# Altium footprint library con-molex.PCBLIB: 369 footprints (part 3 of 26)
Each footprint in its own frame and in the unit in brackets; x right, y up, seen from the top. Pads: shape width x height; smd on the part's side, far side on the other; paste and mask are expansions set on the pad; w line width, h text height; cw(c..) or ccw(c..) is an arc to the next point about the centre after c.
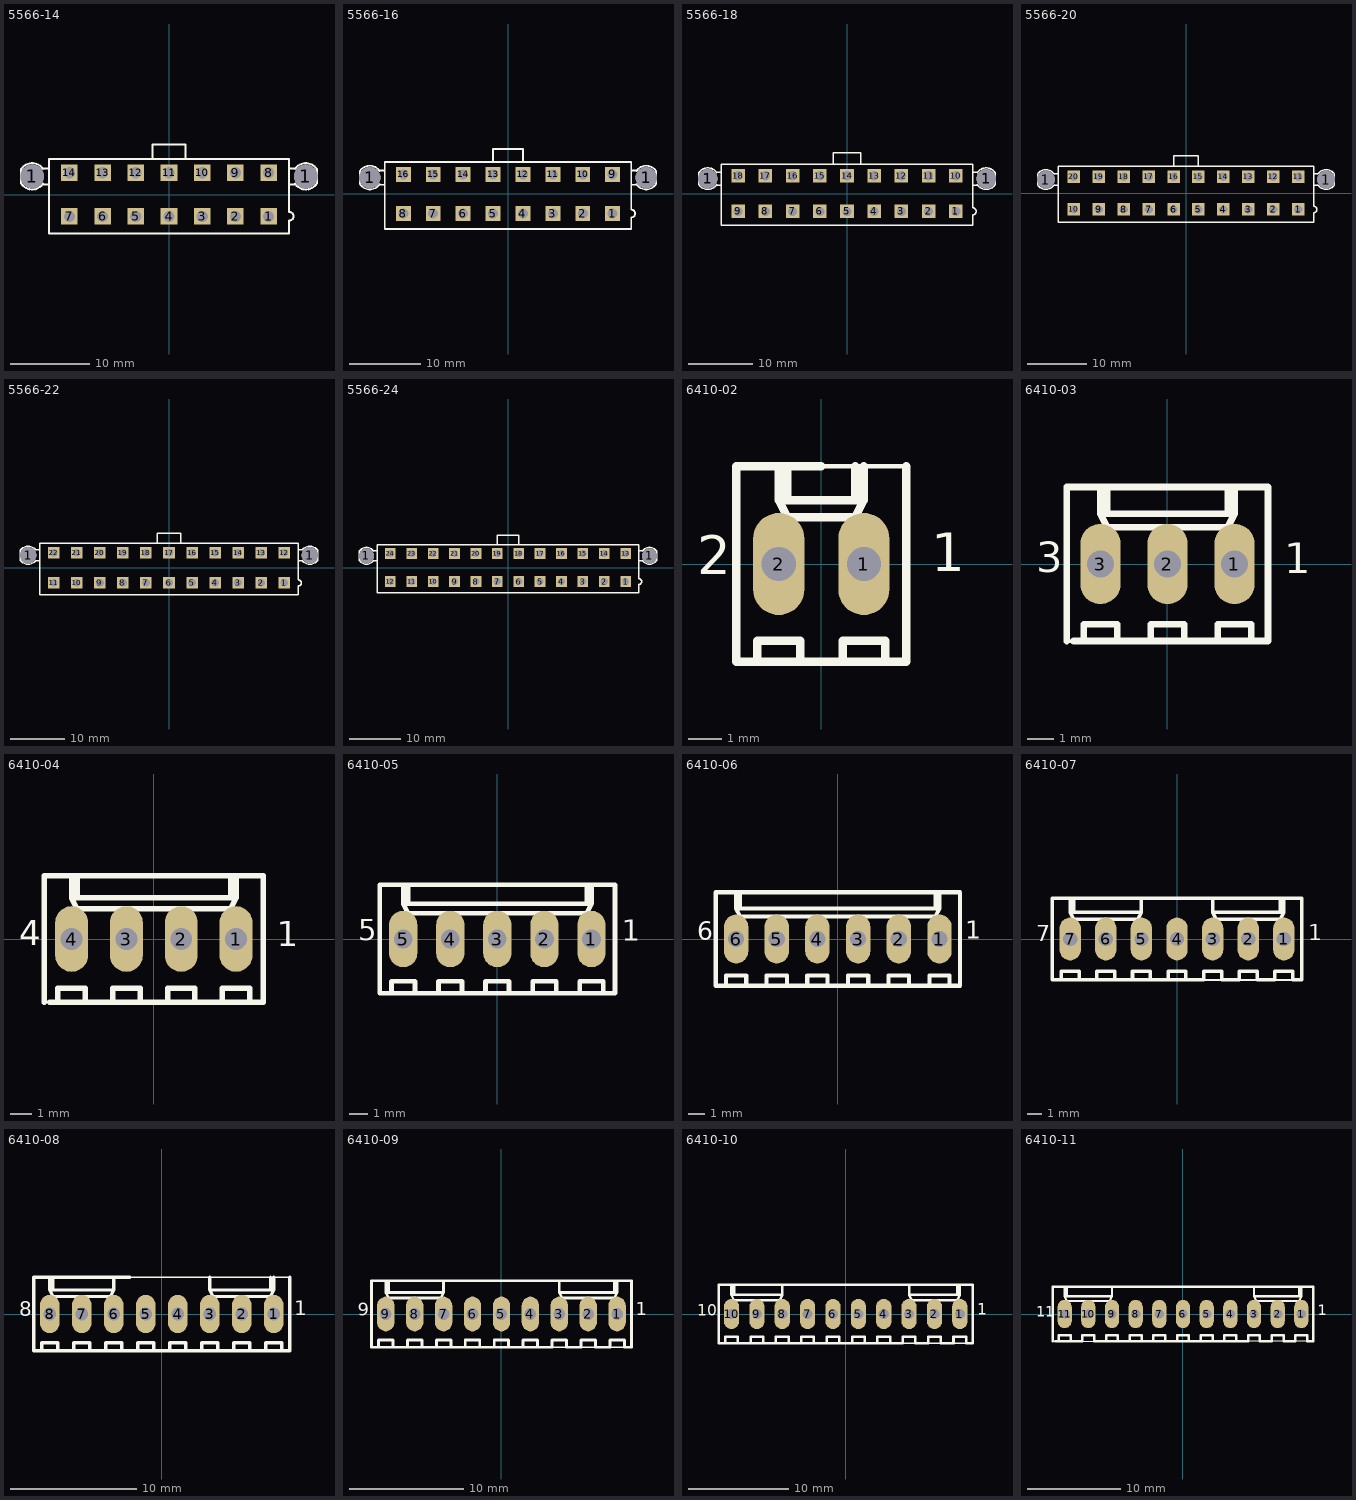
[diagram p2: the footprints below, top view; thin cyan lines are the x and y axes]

## 5566-14 [mm]
pads (16):
  round 3 hole 3: 1(-17.3,2.29) 1(17.3,2.29)
  rect 2.1x2.1 hole 1.4: 1(12.6,-2.75) 2(8.4,-2.75) 3(4.2,-2.75) 4(0,-2.75) 5(-4.2,-2.75) 6(-8.4,-2.75) 7(-12.6,-2.75) 8(12.6,2.75) 9(8.4,2.75) 10(4.2,2.75) 11(0,2.75) 12(-4.2,2.75) 13(-8.4,2.75) 14(-12.6,2.75)
Top Overlay:
  lines w0.254: -16,1.3 -15.3,1.3 ; -16,3.3 -15.3,3.3 ; -15.9,1.4 cw(c-17.3,2.3) -18.7,1.4 -18.7,3.2 cw(c-17.3,2.3) -15.9,3.2 ; -2.1,4.6 -2.1,6.3 2.1,6.3 2.1,4.6 ; 15.3,1.3 16,1.3 ; 15.3,3.3 16,3.3 ; 15.9,1.4 ccw(c17.3,2.3) 18.7,1.4 18.7,3.2 ccw(c17.3,2.3) 15.9,3.2 ; -15.2,-4.9 15.2,-4.9 15.2,-3.3 ccw(c15.2,-2.75) 15.2,-2.2 15.2,4.5 -15.2,4.5 -15.2,-4.9

## 5566-16 [mm]
pads (18):
  round 3 hole 3: 1(-19.4,2.29) 1(19.4,2.29)
  rect 2.1x2.1 hole 1.4: 1(14.7,-2.75) 2(10.5,-2.75) 3(6.3,-2.75) 4(2.1,-2.75) 5(-2.1,-2.75) 6(-6.3,-2.75) 7(-10.5,-2.75) 8(-14.7,-2.75) 9(14.7,2.75) 10(10.5,2.75) 11(6.3,2.75) 12(2.1,2.75) 13(-2.1,2.75) 14(-6.3,2.75) 15(-10.5,2.75) 16(-14.7,2.75)
Top Overlay:
  lines w0.254: -18.1,1.3 -17.4,1.3 ; -18.1,3.3 -17.4,3.3 ; -18,1.4 cw(c-19.4,2.3) -20.8,1.4 -20.8,3.2 cw(c-19.4,2.3) -18,3.2 ; -2.1,4.6 -2.1,6.3 2.1,6.3 2.1,4.6 ; 17.4,1.3 18.1,1.3 ; 17.4,3.3 18.1,3.3 ; 18,1.4 ccw(c19.4,2.3) 20.8,1.4 20.8,3.2 ccw(c19.4,2.3) 18,3.2 ; -17.3,-4.9 17.3,-4.9 17.3,-3.3 ccw(c17.3,-2.75) 17.3,-2.2 17.3,4.5 -17.3,4.5 -17.3,-4.9

## 5566-18 [mm]
pads (20):
  round 3 hole 3: 1(-21.5,2.29) 1(21.5,2.29)
  rect 2.1x2.1 hole 1.4: 1(16.8,-2.75) 2(12.6,-2.75) 3(8.4,-2.75) 4(4.2,-2.75) 5(0,-2.75) 6(-4.2,-2.75) 7(-8.4,-2.75) 8(-12.6,-2.75) 9(-16.8,-2.75) 10(16.8,2.75) 11(12.6,2.75) 12(8.4,2.75) 13(4.2,2.75) 14(0,2.75) 15(-4.2,2.75) 16(-8.4,2.75) 17(-12.6,2.75) 18(-16.8,2.75)
Top Overlay:
  lines w0.254: -20.2,1.3 -19.5,1.3 ; -20.2,3.3 -19.5,3.3 ; -20.1,1.4 cw(c-21.5,2.3) -22.9,1.4 -22.9,3.2 cw(c-21.5,2.3) -20.1,3.2 ; -2.1,4.6 -2.1,6.3 2.1,6.3 2.1,4.6 ; 19.5,1.3 20.2,1.3 ; 19.5,3.3 20.2,3.3 ; 20.1,1.4 ccw(c21.5,2.3) 22.9,1.4 22.9,3.2 ccw(c21.5,2.3) 20.1,3.2 ; -19.4,-4.9 19.4,-4.9 19.4,-3.3 ccw(c19.4,-2.75) 19.4,-2.2 19.4,4.5 -19.4,4.5 -19.4,-4.9

## 5566-20 [mm]
pads (22):
  round 3 hole 3: 1(-23.6,2.29) 1(23.6,2.29)
  rect 2.1x2.1 hole 1.4: 1(18.9,-2.75) 2(14.7,-2.75) 3(10.5,-2.75) 4(6.3,-2.75) 5(2.1,-2.75) 6(-2.1,-2.75) 7(-6.3,-2.75) 8(-10.5,-2.75) 9(-14.7,-2.75) 10(-18.9,-2.75) 11(18.9,2.75) 12(14.7,2.75) 13(10.5,2.75) 14(6.3,2.75) 15(2.1,2.75) 16(-2.1,2.75) 17(-6.3,2.75) 18(-10.5,2.75) 19(-14.7,2.75) 20(-18.9,2.75)
Top Overlay:
  lines w0.254: -22.3,1.3 -21.6,1.3 ; -22.3,3.3 -21.6,3.3 ; -22.2,1.4 cw(c-23.6,2.3) -25,1.4 -25,3.2 cw(c-23.6,2.3) -22.2,3.2 ; -2.1,4.6 -2.1,6.3 2.1,6.3 2.1,4.6 ; 21.6,1.3 22.3,1.3 ; 21.6,3.3 22.3,3.3 ; 22.2,1.4 ccw(c23.6,2.3) 25,1.4 25,3.2 ccw(c23.6,2.3) 22.2,3.2 ; -21.5,-4.9 21.5,-4.9 21.5,-3.3 ccw(c21.5,-2.75) 21.5,-2.2 21.5,4.5 -21.5,4.5 -21.5,-4.9

## 5566-22 [mm]
pads (24):
  round 3 hole 3: 1(-25.7,2.29) 1(25.7,2.29)
  rect 2.1x2.1 hole 1.4: 1(21,-2.75) 2(16.8,-2.75) 3(12.6,-2.75) 4(8.4,-2.75) 5(4.2,-2.75) 6(0,-2.75) 7(-4.2,-2.75) 8(-8.4,-2.75) 9(-12.6,-2.75) 10(-16.8,-2.75) 11(-21,-2.75) 12(21,2.75) 13(16.8,2.75) 14(12.6,2.75) 15(8.4,2.75) 16(4.2,2.75) 17(0,2.75) 18(-4.2,2.75) 19(-8.4,2.75) 20(-12.6,2.75) 21(-16.8,2.75) 22(-21,2.75)
Top Overlay:
  lines w0.254: -24.4,1.3 -23.7,1.3 ; -24.4,3.3 -23.7,3.3 ; -24.3,1.4 cw(c-25.7,2.3) -27.1,1.4 -27.1,3.2 cw(c-25.7,2.3) -24.3,3.2 ; -2.1,4.6 -2.1,6.3 2.1,6.3 2.1,4.6 ; 23.7,1.3 24.4,1.3 ; 23.7,3.3 24.4,3.3 ; 24.3,1.4 ccw(c25.7,2.3) 27.1,1.4 27.1,3.2 ccw(c25.7,2.3) 24.3,3.2 ; -23.6,-4.9 23.6,-4.9 23.6,-3.3 ccw(c23.6,-2.75) 23.6,-2.2 23.6,4.5 -23.6,4.5 -23.6,-4.9

## 5566-24 [mm]
pads (26):
  round 3 hole 3: 1(-27.8,2.29) 1(27.8,2.29)
  rect 2.1x2.1 hole 1.4: 1(23.1,-2.75) 2(18.9,-2.75) 3(14.7,-2.75) 4(10.5,-2.75) 5(6.3,-2.75) 6(2.1,-2.75) 7(-2.1,-2.75) 8(-6.3,-2.75) 9(-10.5,-2.75) 10(-14.7,-2.75) 11(-18.9,-2.75) 12(-23.1,-2.75) 13(23.1,2.75) 14(18.9,2.75) 15(14.7,2.75) 16(10.5,2.75) 17(6.3,2.75) 18(2.1,2.75) 19(-2.1,2.75) 20(-6.3,2.75) 21(-10.5,2.75) 22(-14.7,2.75) 23(-18.9,2.75) 24(-23.1,2.75)
Top Overlay:
  lines w0.254: -26.5,1.3 -25.8,1.3 ; -26.5,3.3 -25.8,3.3 ; -26.4,1.4 cw(c-27.8,2.3) -29.2,1.4 -29.2,3.2 cw(c-27.8,2.3) -26.4,3.2 ; -2.1,4.6 -2.1,6.3 2.1,6.3 2.1,4.6 ; 25.8,1.3 26.5,1.3 ; 25.8,3.3 26.5,3.3 ; 26.4,1.4 ccw(c27.8,2.3) 29.2,1.4 29.2,3.2 ccw(c27.8,2.3) 26.4,3.2 ; -25.7,-4.9 25.7,-4.9 25.7,-3.3 ccw(c25.7,-2.75) 25.7,-2.2 25.7,4.5 -25.7,4.5 -25.7,-4.9

## 6410-02 [mil]
pads (2):
  oval 60x120 hole 40: 1(50,0) 2(-50,0)
Top Overlay:
  lines w5: -90,-115 -75,-115 ; -50,100 -50,115 -40,115 ; 0,-115 25,-115 ; 0,115 100,115 ; 75,-115 100,-115
  lines w10: -40,115 -40,75 ; 0,-115 -100,-115 ; 0,115 -50,115 ; 40,115 40,75 ; 50,115 50,75 ; 100,115 100,0 100,-115 75,-115 ; -100,-115 -100,0 -100,115 -50,115 ; -100,-115 -75,-115 -75,-90 -25,-90 -25,-115 25,-115 ; -50,75 -50,115 ; -50,75 -40,75 ; -50,75 -40,55 40,55 50,75 ; -40,75 40,75 ; 25,-115 75,-115 ; 25,-115 25,-90 75,-90 75,-115 ; 40,75 50,75
  text "1" at 128.94,-24.06 h77.5
  text "2" at -146.06,-27.06 h77.5
Mechanical 16:
  rectangle: -60,-10 -40,10
  rectangle: 40,-10 60,10

## 6410-03 [mil]
pads (3):
  oval 60x120 hole 40: 1(100,0) 2(0,0) 3(-100,0)
Top Overlay:
  lines w5: -150,-115 -50,-115 -25,-115 ; -100,100 -100,115 -90,115
  lines w10: -150,-115 -150,0 -150,115 -100,115 ; -140,-115 -125,-115 ; -90,115 -90,75 ; 90,115 90,75 ; 100,115 100,75 ; -125,-115 -125,-90 -75,-90 -75,-115 ; -125,-115 -75,-115 ; -100,75 -100,115 ; -100,75 -90,75 ; -100,75 -90,55 90,55 100,75 ; -100,115 -50,115 150,115 150,0 150,-115 125,-115 ; -90,75 90,75 ; -75,-115 -25,-115 ; -25,-115 25,-115 ; -25,-115 -25,-90 25,-90 25,-115 ; 25,-115 75,-115 ; 75,-115 125,-115 ; 75,-115 75,-90 125,-90 125,-115 ; 90,75 100,75
  text "1" at 173.94,-29.06 h77.5
  text "3" at -196.06,-27.06 h77.5
Mechanical 16:
  rectangle: -110,-10 -90,10
  rectangle: -10,-10 10,10
  rectangle: 90,-10 110,10

## 6410-04 [mil]
pads (4):
  oval 60x120 hole 40: 1(150,0) 2(50,0) 3(-50,0) 4(-150,0)
Top Overlay:
  lines w5: -200,-115 -105,-115 ; -150,100 -150,115 -140,115
  lines w10: -200,-115 -200,0 -200,115 -150,115 ; -190,-115 -175,-115 ; -140,115 -140,75 ; -105,-115 200,-115 ; 140,115 140,75 ; 150,115 150,75 ; -175,-115 -175,-90 -125,-90 -125,-115 -75,-115 -75,-90 -25,-90 -25,-115 ; -175,-115 -25,-115 ; -150,75 -150,115 ; -150,75 -140,75 ; -150,75 -140,55 140,55 150,75 ; -150,115 -100,115 200,115 200,0 200,-115 ; -140,75 140,75 ; -25,-115 25,-115 25,-90 75,-90 75,-115 125,-115 125,-90 175,-90 175,-115 200,-115 ; 140,75 150,75
  text "1" at 223.94,-29.06 h77.5
  text "4" at -246.06,-27.06 h77.5
Mechanical 16:
  rectangle: -160,-10 -140,10
  rectangle: -60,-10 -40,10
  rectangle: 40,-10 60,10
  rectangle: 140,-10 160,10

## 6410-05 [mil]
pads (5):
  oval 60x120 hole 40: 1(200,0) 2(100,0) 3(0,0) 4(-100,0) 5(-200,0)
Top Overlay:
  lines w5: -200,100 -200,115
  lines w10: -240,-115 -225,-115 -225,-90 -175,-90 -175,-115 -125,-115 -125,-90 -75,-90 -75,-115 -25,-115 ; 50,-115 -250,-115 -250,0 -250,115 -200,115 ; 190,115 190,75 ; 200,115 200,75 ; -200,75 -200,115 ; -200,75 -190,75 ; -200,75 -190,55 190,55 200,75 ; -200,115 -190,115 ; -190,75 190,75 ; -190,75 -190,115 ; -190,115 50,115 250,115 250,0 250,-115 225,-115 ; -25,-115 -25,-90 25,-90 25,-115 ; -25,-115 25,-115 ; 25,-115 75,-115 ; 75,-115 125,-115 ; 75,-115 75,-90 125,-90 125,-115 ; 125,-115 175,-115 ; 175,-115 225,-115 ; 175,-115 175,-90 225,-90 225,-115 ; 190,75 200,75
  text "1" at 263.94,-19.06 h77.5
  text "5" at -296.06,-17.06 h77.5
Mechanical 16:
  rectangle: -10,-10 10,10
  rectangle: 90,-10 110,10
  rectangle: 190,-10 210,10
  rectangle: -110,-10 -90,10
  rectangle: -210,-10 -190,10

## 6410-06 [mil]
pads (6):
  oval 60x120 hole 40: 1(250,0) 2(150,0) 3(50,0) 4(-50,0) 5(-150,0) 6(-250,0)
Top Overlay:
  lines w5: -250,100 -250,115
  lines w10: -290,-115 -275,-115 -275,-90 -225,-90 -225,-115 -175,-115 -175,-90 -125,-90 -125,-115 -75,-115 -75,-90 -25,-90 -25,-115 25,-115 25,-90 75,-90 75,-115 125,-115 125,-90 175,-90 175,-115 225,-115 225,-90 275,-90 275,-115 300,-115 ; 240,115 240,75 ; 250,115 250,75 ; -250,75 -250,115 ; -250,75 -240,75 ; -250,75 -240,55 240,55 250,75 ; -250,115 -300,115 -300,0 -300,-115 -5,-115 300,-115 ; -250,115 -240,115 ; -240,75 240,75 ; -240,75 -240,115 ; -240,115 0,115 300,115 300,0 300,-115 ; 240,75 250,75
  text "1" at 313.94,-14.06 h77.5
  text "6" at -346.06,-17.06 h77.5
Mechanical 16:
  rectangle: -260,-10 -240,10
  rectangle: -160,-10 -140,10
  rectangle: -60,-10 -40,10
  rectangle: 40,-10 60,10
  rectangle: 140,-10 160,10
  rectangle: 240,-10 260,10

## 6410-07 [mil]
pads (7):
  oval 60x120 hole 40: 1(300,0) 2(200,0) 3(100,0) 4(0,0) 5(-100,0) 6(-200,0) 7(-300,0)
Top Overlay:
  lines w5: -300,100 -300,115 ; -55,-115 350,-115
  lines w10: -340,-115 -325,-115 -325,-90 -275,-90 -275,-115 -225,-115 -225,-90 -175,-90 -175,-115 -125,-115 -125,-90 -75,-90 -75,-115 75,-115 75,-90 125,-90 125,-115 175,-115 175,-90 225,-90 225,-115 275,-115 275,-90 325,-90 325,-115 350,-115 350,0 350,115 -50,115 -100,115 ; -55,-115 -350,-115 -350,0 -350,115 -300,115 ; -25,-115 -25,-90 25,-90 25,-115 ; 100,115 100,75 ; 290,115 290,75 ; 300,115 300,75 ; -300,75 -300,115 ; -300,75 -290,75 ; -300,75 -290,55 -110,55 -100,75 ; -300,115 -290,115 ; -290,75 -100,75 ; -290,75 -290,115 ; -290,115 -100,115 ; -100,75 -100,115 ; 100,75 290,75 ; 100,75 110,55 290,55 300,75 ; 290,75 300,75
  text "1" at 368.94,-19.06 h77.5
  text "7" at -396.06,-22.06 h77.5
Mechanical 16:
  rectangle: 90,-10 110,10
  rectangle: 190,-10 210,10
  rectangle: 290,-10 310,10
  rectangle: -10,-10 10,10
  rectangle: -110,-10 -90,10
  rectangle: -310,-10 -290,10
  rectangle: -210,-10 -190,10

## 6410-08 [mil]
pads (8):
  oval 60x120 hole 40: 1(350,0) 2(250,0) 3(150,0) 4(50,0) 5(-50,0) 6(-150,0) 7(-250,0) 8(-350,0)
Top Overlay:
  lines w5: -350,100 -350,115 ; -100,115 400,115
  lines w10: -390,-115 -375,-115 -375,-90 -325,-90 -325,-115 -275,-115 -275,-90 -225,-90 -225,-115 -175,-115 -175,-90 -125,-90 -125,-115 125,-115 125,-90 175,-90 175,-115 225,-115 225,-90 275,-90 275,-115 325,-115 325,-90 375,-90 375,-115 400,-115 ; -100,115 -150,115 ; -75,-115 -75,-90 -25,-90 -25,-115 ; 25,-115 25,-90 75,-90 75,-115 ; 150,115 150,75 ; 340,115 340,75 ; 350,115 350,75 ; 400,115 400,0 400,-115 ; -350,75 -350,115 ; -350,75 -340,75 ; -350,75 -340,55 -160,55 -150,75 ; -350,115 -400,115 -400,0 -400,-115 -105,-115 400,-115 ; -350,115 -340,115 ; -340,75 -150,75 ; -340,75 -340,115 ; -340,115 -150,115 ; -150,75 -150,115 ; 150,75 340,75 ; 150,75 160,55 340,55 350,75 ; 340,75 350,75
  text "1" at 413.94,-19.06 h77.5
  text "8" at -446.06,-22.06 h77.5
Mechanical 16:
  rectangle: -360,-10 -340,10
  rectangle: -260,-10 -240,10
  rectangle: -160,-10 -140,10
  rectangle: 140,-10 160,10
  rectangle: 240,-10 260,10
  rectangle: 340,-10 360,10
  rectangle: -60,-10 -40,10
  rectangle: 40,-10 60,10

## 6410-09 [mil]
pads (9):
  oval 60x120 hole 40: 1(400,0) 2(300,0) 3(200,0) 4(100,0) 5(0,0) 6(-100,0) 7(-200,0) 8(-300,0) 9(-400,0)
Top Overlay:
  lines w5: -400,100 -400,115 ; -155,-115 450,-115
  lines w10: -440,-115 -425,-115 -425,-90 -375,-90 -375,-115 -325,-115 -325,-90 -275,-90 -275,-115 -225,-115 -225,-90 -175,-90 -175,-115 175,-115 175,-90 225,-90 225,-115 275,-115 275,-90 325,-90 325,-115 375,-115 375,-90 425,-90 425,-115 450,-115 450,0 450,115 -150,115 -200,115 ; -155,-115 -450,-115 -450,0 -450,115 -400,115 ; -125,-115 -125,-90 -75,-90 -75,-115 ; -25,-115 -25,-90 25,-90 25,-115 ; 75,-115 75,-90 125,-90 125,-115 ; 200,115 200,75 ; 390,115 390,75 ; 400,115 400,75 ; -400,75 -400,115 ; -400,75 -390,75 ; -400,75 -390,55 -210,55 -200,75 ; -400,115 -390,115 ; -390,75 -200,75 ; -390,75 -390,115 ; -390,115 -200,115 ; -200,75 -200,115 ; 200,75 390,75 ; 200,75 210,55 390,55 400,75 ; 390,75 400,75
  text "1" at 463.94,-19.06 h77.5
  text "9" at -496.06,-22.06 h77.5
Mechanical 16:
  rectangle: 190,-10 210,10
  rectangle: 290,-10 310,10
  rectangle: 390,-10 410,10
  rectangle: -410,-10 -390,10
  rectangle: 90,-10 110,10
  rectangle: -10,-10 10,10
  rectangle: -310,-10 -290,10
  rectangle: -210,-10 -190,10
  rectangle: -110,-10 -90,10

## 6410-10 [mil]
pads (10):
  oval 60x120 hole 40: 1(450,0) 2(350,0) 3(250,0) 4(150,0) 5(50,0) 6(-50,0) 7(-150,0) 8(-250,0) 9(-350,0) 10(-450,0)
Top Overlay:
  lines w5: -450,100 -450,115 ; -205,-115 500,-115
  lines w10: -490,-115 -475,-115 -475,-90 -425,-90 -425,-115 -375,-115 -375,-90 -325,-90 -325,-115 -275,-115 -275,-90 -225,-90 -225,-115 225,-115 225,-90 275,-90 275,-115 325,-115 325,-90 375,-90 375,-115 425,-115 425,-90 475,-90 475,-115 500,-115 500,0 500,115 -200,115 -250,115 ; -205,-115 -500,-115 -500,0 -500,115 -450,115 ; -175,-115 -175,-90 -125,-90 -125,-115 ; -75,-115 -75,-90 -25,-90 -25,-115 ; 25,-115 25,-90 75,-90 75,-115 ; 125,-115 125,-90 175,-90 175,-115 ; 250,115 250,75 ; 440,115 440,75 ; 450,115 450,75 ; -450,75 -450,115 ; -450,75 -440,75 ; -450,75 -440,55 -260,55 -250,75 ; -450,115 -440,115 ; -440,75 -250,75 ; -440,75 -440,115 ; -440,115 -250,115 ; -250,75 -250,115 ; 250,75 440,75 ; 250,75 260,55 440,55 450,75 ; 440,75 450,75
  text "1" at 518.94,-19.06 h77.5
  text "10" at -586.06,-22.06 h77.5
Mechanical 16:
  rectangle: -460,-10 -440,10
  rectangle: -360,-10 -340,10
  rectangle: -260,-10 -240,10
  rectangle: 240,-10 260,10
  rectangle: 340,-10 360,10
  rectangle: 440,-10 460,10
  rectangle: -160,-10 -140,10
  rectangle: 140,-10 160,10
  rectangle: 40,-10 60,10
  rectangle: -60,-10 -40,10

## 6410-11 [mil]
pads (11):
  oval 60x120 hole 40: 1(500,0) 2(400,0) 3(300,0) 4(200,0) 5(100,0) 6(0,0) 7(-100,0) 8(-200,0) 9(-300,0) 10(-400,0) 11(-500,0)
Top Overlay:
  lines w5: -550,-115 -355,-115 550,-115 ; -500,100 -500,115
  lines w10: -550,-115 -550,0 -550,115 -500,115 ; -540,-115 -525,-115 ; -325,-115 -325,-90 -275,-90 -275,-115 ; -225,-115 -225,-90 -175,-90 -175,-115 ; -125,-115 -125,-90 -75,-90 -75,-115 ; -25,-115 -25,-90 25,-90 25,-115 ; 75,-115 75,-90 125,-90 125,-115 ; 175,-115 175,-90 225,-90 225,-115 ; 300,115 300,75 ; 490,115 490,75 ; 500,115 500,75 ; -525,-115 -475,-115 ; -525,-115 -525,-90 -475,-90 -475,-115 ; -500,75 -500,115 ; -500,75 -490,75 ; -500,75 -490,55 -310,55 -300,75 ; -500,115 -490,115 ; -490,75 -300,75 ; -490,75 -490,115 ; -490,115 -300,115 ; -475,-115 -425,-115 -425,-90 -375,-90 -375,-115 275,-115 275,-90 325,-90 325,-115 375,-115 375,-90 425,-90 425,-115 475,-115 475,-90 525,-90 525,-115 550,-115 550,0 550,115 -250,115 -300,115 ; -300,75 -300,115 ; 300,75 490,75 ; 300,75 310,55 490,55 500,75 ; 490,75 500,75
  text "1" at 568.94,-19.06 h77.5
  text "11" at -621.06,-27.06 h77.5
Mechanical 16:
  rectangle: -510,-10 -490,10
  rectangle: -410,-10 -390,10
  rectangle: 290,-10 310,10
  rectangle: 390,-10 410,10
  rectangle: 490,-10 510,10
  rectangle: -310,-10 -290,10
  rectangle: 190,-10 210,10
  rectangle: 90,-10 110,10
  rectangle: -210,-10 -190,10
  rectangle: -110,-10 -90,10
  rectangle: -10,-10 10,10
